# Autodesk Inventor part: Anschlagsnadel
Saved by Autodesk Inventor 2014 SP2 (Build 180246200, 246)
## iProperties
Created: 2015-07
Part Number: Anschlagsnadel
Material: Generisch
Document SubType Name: Modeling
Designer: e_krauts
Density: 1 g/cm^3
Appearance: Vorgabe
Author: e_krauts
Sending System: SolidWorks 2011
Last Author: e_boekem
Sachnummer: NWS 100-00-07
Erstellt durch: XYZ
Werkstoff: 10SPb20
Einheit: Stck.
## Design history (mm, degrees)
node "Anschlagsnadel.ipt1"
node "Rotation1"
node "Basis1"
